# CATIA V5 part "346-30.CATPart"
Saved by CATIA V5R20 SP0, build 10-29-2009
Part number: 346-30
Definition: NONE
Nomenclature: 346-30
Source: Unknown
Description: 346-30  
Bounding box of the stored display mesh (mm): x 0 to 72, y -36 to 36, z -36 to 36
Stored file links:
  C:\Users\Utente\Desktop\IO LAVORO\3D X SITO CF\X SITO\3D files 346\346-30.CATPart
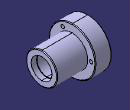
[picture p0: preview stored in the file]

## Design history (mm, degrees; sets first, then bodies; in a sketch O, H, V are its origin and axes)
Body1 "346-30" (main body)
  Solid1: solid without history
